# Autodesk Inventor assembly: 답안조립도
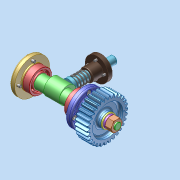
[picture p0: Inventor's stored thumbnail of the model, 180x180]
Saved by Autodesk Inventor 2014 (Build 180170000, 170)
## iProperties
Created: 2026-06
Part Number: 답안조립도
Document SubType Name: Assembly
Designer: dg
Mass: 1454.24 g
Surface Area: 1270.34 cm^2
Volume: 333.435 cm^3
Density: 4.3614 g/cm^3
Author: dg
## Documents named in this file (17)
- C:\Users\dg\Desktop\660603V1003\답안조립도.iam
- C:\Users\dg\Desktop\660603V1003\가져온 구성요소\본체\본체.ipt
- C:\Users\dg\Desktop\660603V1003\가져온 구성요소\6각 구멍붙이 볼트 M3x8\6각 구멍붙이 볼트 M3x8.ipt
- C:\Users\dg\Desktop\660603V1003\가져온 구성요소\6각 구멍붙이 볼트 M4x8\6각 구멍붙이 볼트 M4x8.ipt
- C:\Users\dg\Desktop\660603V1003\가져온 구성요소\6각 너트 M10x1\6각 너트 M10x1.ipt
- C:\Users\dg\Desktop\660603V1003\가져온 구성요소\가이드 부시\가이드 부시.ipt
- C:\Users\dg\Desktop\660603V1003\가져온 구성요소\깊은 홈 볼 베어링 6003\깊은 홈 볼 베어링 6003.ipt
- C:\Users\dg\Desktop\660603V1003\가져온 구성요소\뒷 커버\뒷 커버.ipt
- C:\Users\dg\Desktop\660603V1003\가져온 구성요소\스퍼 기어\스퍼 기어.ipt
- C:\Users\dg\Desktop\660603V1003\가져온 구성요소\스프링 와셔 M10\스프링 와셔 M10.ipt
- C:\Users\dg\Desktop\660603V1003\가져온 구성요소\슬라이더\슬라이더.ipt
- C:\Users\dg\Desktop\660603V1003\가져온 구성요소\앞 커버\앞 커버.ipt
- C:\Users\dg\Desktop\660603V1003\가져온 구성요소\오일 실 17 30 8\오일 실 17 30 8.ipt
- C:\Users\dg\Desktop\660603V1003\가져온 구성요소\캠 축\캠 축.ipt
- C:\Users\dg\Desktop\660603V1003\가져온 구성요소\평와셔 M10\평와셔 M10.ipt
- C:\Users\dg\Desktop\660603V1003\가져온 구성요소\평행 키 3x3x14\평행 키 3x3x14.ipt
- C:\Users\dg\Desktop\660603V1003\가변스프링.ipt
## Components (15 placed, 5 different names)
1. 6각 너트 M10x1:1
2. 가이드 부시:1
3. 가변스프링:1
4. 6각 구멍붙이 볼트 M4x8:2
5. 6각 구멍붙이 볼트 M4x8:3
6. 6각 구멍붙이 볼트 M4x8:4
7. 6각 구멍붙이 볼트 M4x8:5
8. 6각 구멍붙이 볼트 M4x8:1
9. 6각 구멍붙이 볼트 M4x8:6
10. 6각 구멍붙이 볼트 M4x8:7
11. 6각 구멍붙이 볼트 M4x8:8
12. 6각 구멍붙이 볼트 M3x8:1
13. 6각 구멍붙이 볼트 M3x8:2
14. 6각 구멍붙이 볼트 M3x8:3
15. 6각 구멍붙이 볼트 M3x8:4
